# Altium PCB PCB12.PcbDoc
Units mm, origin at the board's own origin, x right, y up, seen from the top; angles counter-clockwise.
Board outline 101.6 x 53.34 mm, 4 copper layers (TOP, GND, SIG, BOTTOM), stack 1.586 mm thick; 3 components, 243 nets, 56 pads, 0 vias.
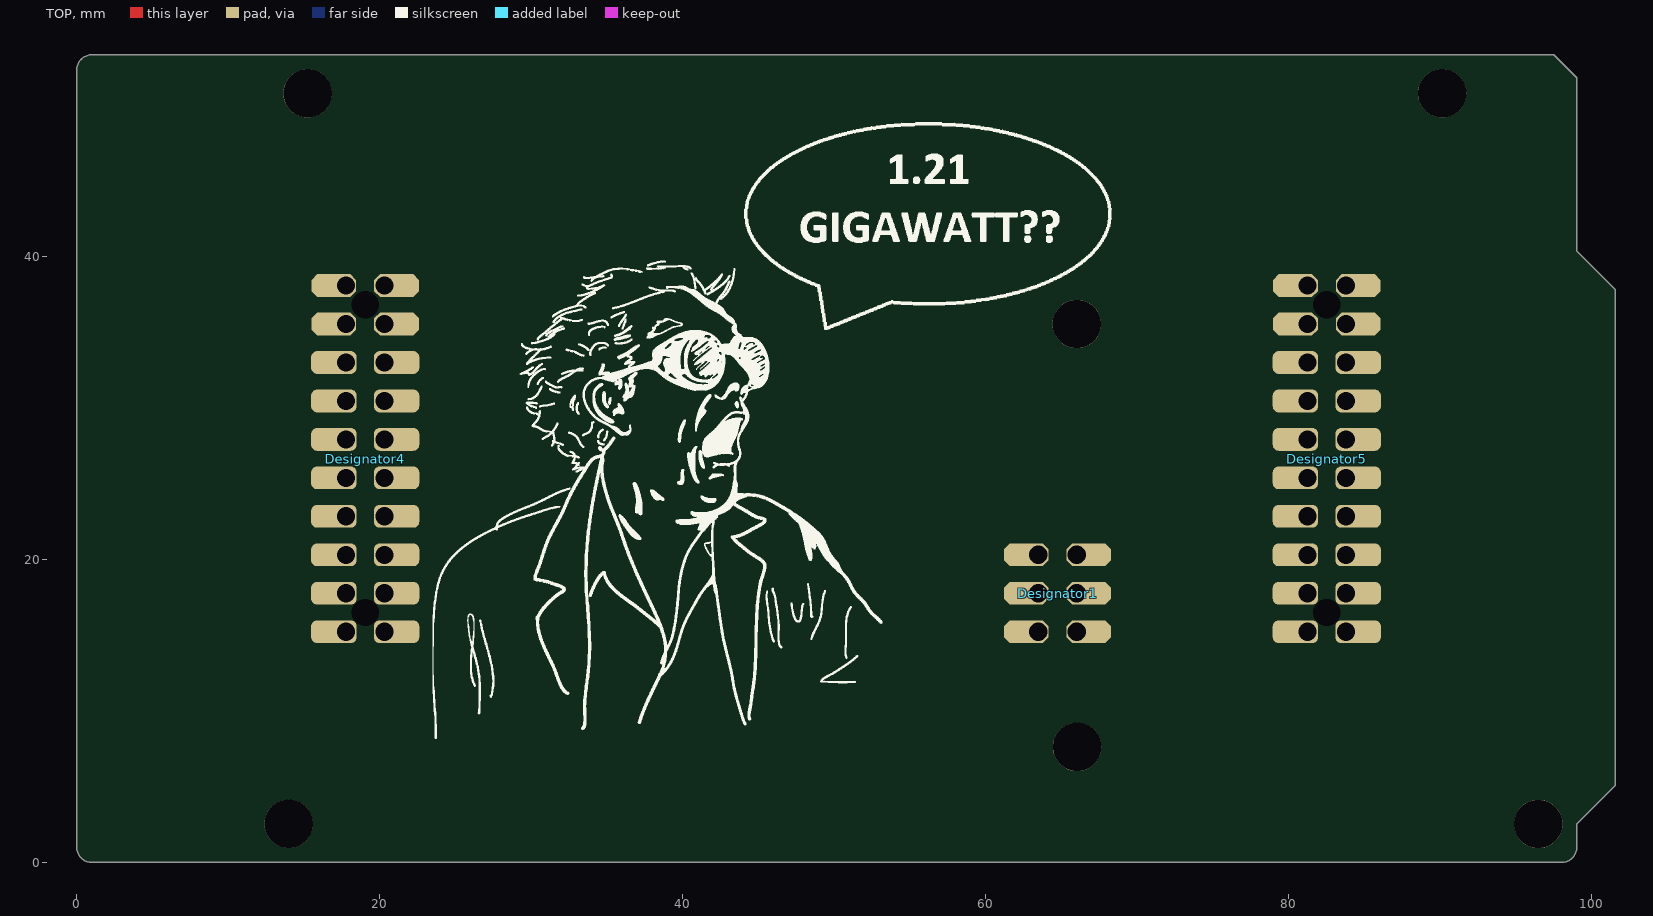
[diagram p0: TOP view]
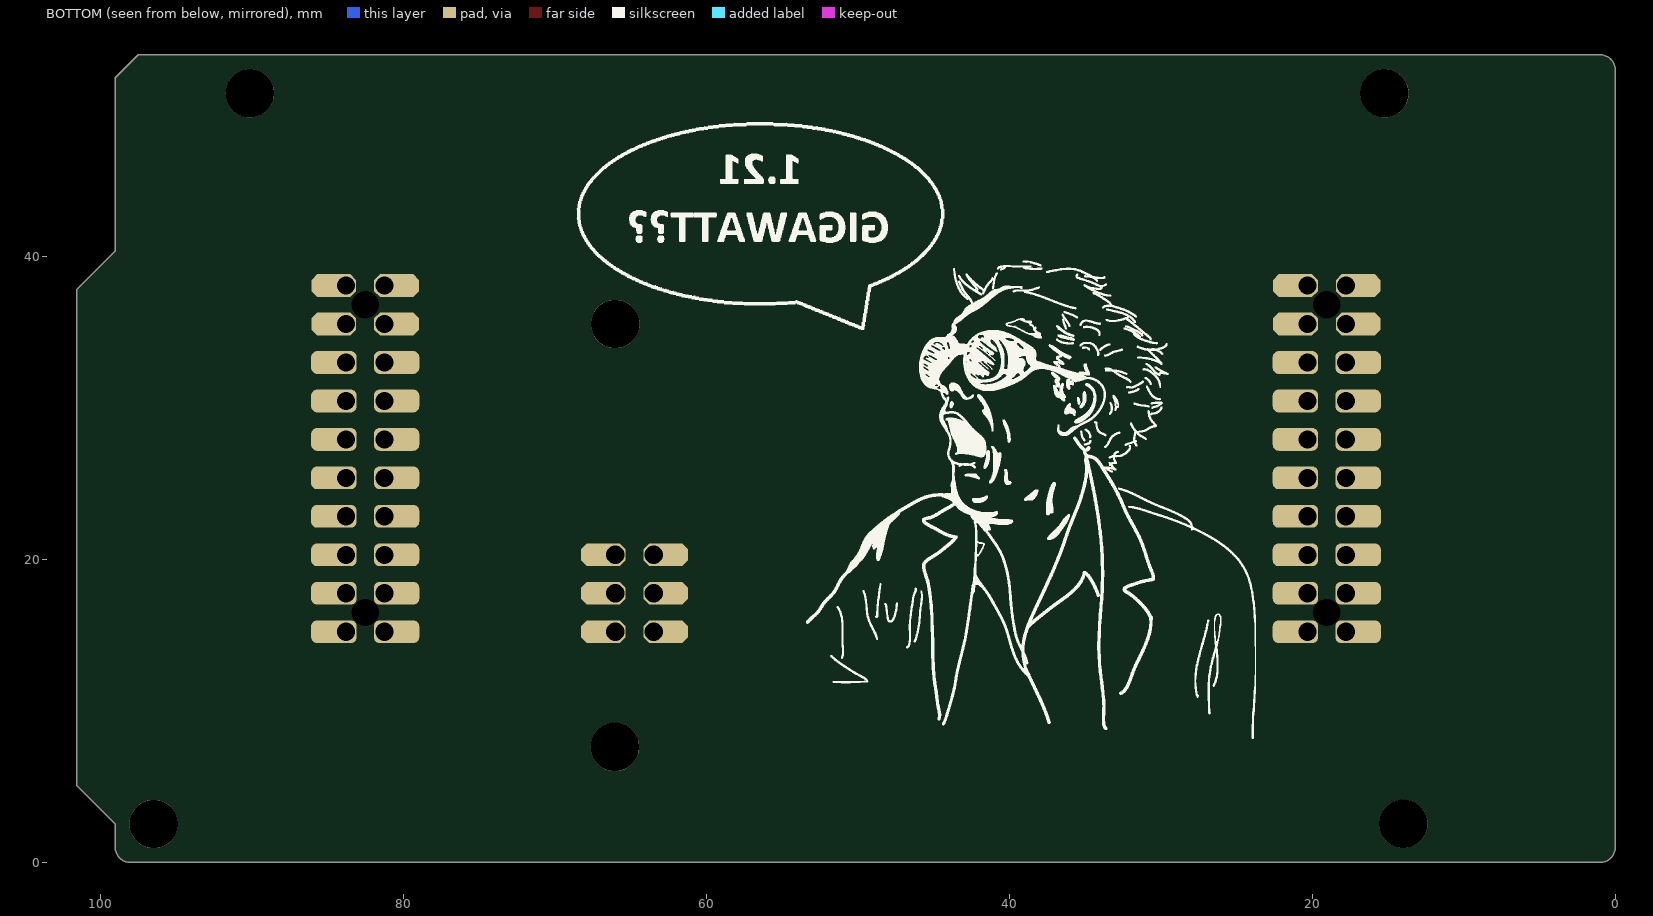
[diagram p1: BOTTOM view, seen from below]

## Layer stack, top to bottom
Top Solder: solder mask 0.0102, Solder Resist, Dk 3.5
TOP: signal copper 0.018
Dielectric 1: prepreg 0.14, PP-014, Dk 4.2
GND: signal copper 0.035
Dielectric2: core 1.2, FR-4, Dk 4.8
SIG: signal copper 0.035
Dielectric3: prepreg 0.14, PP-014, Dk 4.2
BOTTOM: signal copper 0.018
Bottom Solder: solder mask 0.0102, Solder Resist, Dk 3.5

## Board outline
0,1 0,52.34 cw(c1,52.34) 1,53.34 97.536,53.34 99.06,51.816 99.06,40.386 101.6,37.846 101.6,5.08 99.06,2.54 99.06,1 cw(c98.06,1) 98.06,0 1,0 cw(c1,1)

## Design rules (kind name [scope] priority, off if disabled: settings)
BoardOutlineClearance Silks [(OnLayer('Top Overlay') OR OnLayer('Bottom Overlay'))] p1: gap=0.1 ignorepadtopadclearanceinfootprint=FALSE
BoardOutlineClearance [All] p2: gap=0.3 ignorepadtopadclearanceinfootprint=FALSE
Clearance COPPER_0.3mm [All] p1: gap=0.127 ignorepadtopadclearanceinfootprint=FALSE except(0.3: Arc-Fill Arc-Poly Arc-Region Track-Fill Track-Poly Track-Region SMDPad-Fill SMDPad-Poly SMDPad-Region THPad-Fill THPad-Poly THPad-Region Via-Fill Via-Poly Via-Region Fill-Fill Fill-Poly Fill-Region Poly-Poly Poly-Region Region-Region)
Clearance "Generic clearance 0.127mm" [All] p2: gap=0.127 ignorepadtopadclearanceinfootprint=FALSE
ComponentClearance [All] p1: gap=0.2 collisioncheckmode=3 verticalgap=0 showdistances=TRUE
DiffPairsRouting USB [InDifferentialPairClass('USB')] p1: maxlimit=0.254 minlimit=0.15 mostfreqgap=0.254 toplayer_maxgap=0.15 toplayer_prefgap=0.15 toplayer_minwidth=0.15 toplayer_maxwidth=0.21 toplayer_prefwidth=0.2 midlayer2_mingap=0.24 midlayer2_maxgap=0.24 midlayer2_prefgap=0.24 midlayer2_minwidth=0.15 midlayer2_maxwidth=0.15 midlayer2_prefwidth=0.15 bottomlayer_maxgap=0.15 bottomlayer_prefgap=0.15 bottomlayer_minwidth=0.15 bottomlayer_maxwidth=0.21 bottomlayer_prefwidth=0.2 impedanceprofiledriven=TRUE impedanceprofileid={E6B00C31-4C8E-439C-824F-D2B2CDC26F9C} impedanceprofilevalue=90.000000 maxuncoupledlength=12.7
Height [All] p1: minheight=0 maxheight=30 prefheight=12.7
HoleSize [All] p1: absolutevalues=TRUE maxlimit=20 minlimit=0.3 maxpercent=80.000 minpercent=20.000
HoleToHoleClearance [All] p1: gap=0.25 allowstackedmicrovias=FALSE
MinimumAnnularRing [All] p1: minimumring=0.15
PlaneConnect [All] p1: pad.planeconnectstyle=Relief pad.reliefexpansion=0.508 pad.reliefentries=4 pad.reliefconductorwidth=0.254 pad.reliefairgap=0.254 via.planeconnectstyle=Direct via.reliefexpansion=0.508 via.reliefentries=4 via.reliefconductorwidth=0.254 via.reliefairgap=0.254
PolygonConnect [All] p1: thpad.connectstyle=Relief thpad.reliefconductorwidth=0.2 thpad.reliefentries=4 thpad.polygonreliefangle="90 Angle" thpad.airgapwidth=0.254 smdpad.connectstyle=Relief smdpad.reliefconductorwidth=0.2 smdpad.reliefentries=4 smdpad.polygonreliefangle="90 Angle" smdpad.airgapwidth=0.254 via.connectstyle=Direct via.reliefconductorwidth=0.254 via.reliefentries=4 via.polygonreliefangle="90 Angle" via.airgapwidth=0.254
RoomDefinition AUDIO [InComponentClass('AUDIO')] p1: confinementstyle=ConfineIn formatcopy=TRUE lockcomponents=FALSE outline 102.7,0.5 179.2,0.5 179.2,30 102.7,30
RoomDefinition Wifi [InComponentClass('Wifi')] p2: confinementstyle=ConfineIn formatcopy=TRUE lockcomponents=FALSE outline -40.4,-40.4 10.4,-40.4 10.4,-15 -40.4,-15
RoomDefinition TOP [InComponentClass('TOP')] p3: confinementstyle=ConfineIn formatcopy=TRUE lockcomponents=FALSE outline 102.7,1.5 112.4,1.5 112.4,12.5 102.7,12.5
RoomDefinition HEADERS [InComponentClass('HEADERS')] p4: confinementstyle=ConfineIn formatcopy=TRUE lockcomponents=FALSE outline 103.6,3.6 145.6,3.6 145.6,51.6 103.6,51.6
RoomDefinition STM32H747 [InComponentClass('STM32H747')] p5: confinementstyle=ConfineIn formatcopy=TRUE lockcomponents=FALSE outline 57.6,-10.4 61.6,-10.4 61.6,-6.4 57.6,-6.4
RoutingVias StandardVias [All] p1: holewidth=0.2 width=0.4 viastyle="Through Hole" minholewidth=0.2 minwidth=0.4 maxholewidth=0.2 maxwidth=0.4
SMDToCorner [All] p1: distance=39370
SilkToSilkClearance [All] p1: silktosilkclearance=0.2
SilkToSolderMaskClearance [IsPad] p1: minsilkscreentomaskgap=0.15 clearancetoexposedcopper=TRUE
SolderMaskExpansion VIAtented [IsVia] p1: expansion=0.102 istentingtop=TRUE
SolderMaskExpansion [All] p2: expansion=0.05 istentingtop=FALSE
UnRoutedNet [All] p1: checkbadconnections=TRUE
ViasUnderSMD [All] p1: allowed=FALSE
Width StandardTraces [All] p1: maxlimit=5 minlimit=0.127 preferedwidth=0.15
21 further rules are at their usual default settings.

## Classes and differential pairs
net class "50 ohm": NetC1V_1 NetC2V_1
component class Wifi: R18

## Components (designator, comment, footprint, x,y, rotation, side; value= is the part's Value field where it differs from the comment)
Designator1 "Comment" HLE-103-02-F-DV 64.77,17.779 r270 top
Designator4 "Comment" HLE-110-02-F-DV 19.05,26.669 r270 top
Designator5 "Comment" HLE-110-02-F-DV 82.55,26.669 r270 top

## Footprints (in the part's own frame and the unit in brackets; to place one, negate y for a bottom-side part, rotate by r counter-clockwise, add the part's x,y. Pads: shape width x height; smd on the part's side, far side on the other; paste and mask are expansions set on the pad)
HLE-103-02-F-DV [mm]
  oct 1.5x2.95 hole 1.2 copper offset 0,-0.8 mask+0.02: 1(-2.54,-1.27) 3(0,-1.27) 5(2.54,-1.27)
  oct 1.5x2.95 hole 1.2 copper offset 0,0.8 mask+0.02: 2(-2.54,1.27) 4(0,1.27) 6(2.54,1.27)
  body extent -3.81,-3.29 3.81,3.29, height 3.71
HLE-110-02-F-DV [mm]
  round 0 hole 1.8 unplated paste-5: 0(-10.16,0) 0(10.16,0)
  oct 1.5x2.95 hole 1.2 copper offset 0,-0.8 mask+0.02: 1(-11.43,-1.27) 3(-8.89,-1.27)
  oct 1.5x2.95 hole 1.2 copper offset 0,0.8 mask+0.02: 2(-11.43,1.27) 4(-8.89,1.27)
  rrect50% 1.5x3 hole 1.2 copper offset 0,-0.8 mask+0.02: 5(-6.35,-1.27) 7(-3.81,-1.27) 9(-1.27,-1.27) 11(1.27,-1.27) 13(3.81,-1.27) 15(6.356,-1.27) 17(8.89,-1.27) 19(11.43,-1.27)
  rrect50% 1.5x3 hole 1.2 copper offset 0,0.8 mask+0.02: 6(-6.35,1.27) 8(-3.81,1.27) 10(-1.27,1.27) 12(1.27,1.27) 14(3.81,1.27) 16(6.356,1.27) 18(8.89,1.27) 20(11.43,1.27)
  body extent -12.7,-3.29 12.7,3.29, height 3.71

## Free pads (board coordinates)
  round 3.2 hole 3.2 unplated: MH1(96.52,2.54) MH2(15.24,50.8) MH3(90.17,50.8) MH4(13.996,2.553) MH5(66.04,35.56) MH6(66.066,7.633)

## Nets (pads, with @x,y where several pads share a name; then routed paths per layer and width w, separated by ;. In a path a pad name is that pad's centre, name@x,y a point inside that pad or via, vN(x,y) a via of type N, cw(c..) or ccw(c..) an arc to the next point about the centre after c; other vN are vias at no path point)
+1V8: 
+3V1: 
+3V1SW: 
+3V3: 
AIN2A: 
AIN2B: 
AIN3A: 
AIN3B: 
BLE_CTRL_DEVICE_WAKE: 
BLE_CTRL_HOST_WAKE: 
BLE_CTRL_ON: 
DSI_CK_N: 
DSI_CK_P: 
DSI_D0_N: 
DSI_D0_P: 
DSI_D1_N: 
DSI_D1_P: 
GND: 
HP/LINE_OUTA: 
HP/LINE_OUTB: 
HSU_D_N: 
HSU_D_P: 
MICBIAS: 
NetAUDIO_RST_X: 
NetC1_2: 
NetC1V_1: 
NetC2V_1: 
NetC5V_1: 
NetC12_2: 
NetC30_2: 
NetC31_1: 
NetC31_2: 
NetC33_1: 
NetC46_1: 
NetC48_1: 
NetC49_1: 
NetC50_1: 
NetL1_2: 
NetL1V_1: 
NetR2_1: 
NetR3_1: 
NetR4_2: 
NetR6_1: 
NetR7_1: 
NetR8_2: 
NetR9_1: 
NetR10_2: 
NetR12_1: 
NetR34_2: 
NetR35_2: 
NetR46_1: 
NetR46_2: 
NetU1_J1: 
NetU1_K1: 
NetU1V_2: 
NetU1V_3: 
NetU1V_4: 
NetU1V_5: 
NetU1V_8: 
NetU1V_9: 
NetU1V_10: 
NetU1V_11: 
NetU1V_20: 
NetU1V_22: 
NetU1V_23: 
NetU1V_24: 
NetU1V_25: 
NetU1V_26: 
NetU1V_37: 
NetU2_37: 
NetU3_26: 
PA0: 
PA1: 
PA2: 
PA3: 
PA4: 
PA5: 
PA6: 
PA7: 
PA8: 
PA9: 
PA10: 
PA11: 
PA12: 
PA13: 
PA14: 
PA15: 
PB0: 
PB1: 
PB2: 
PB3: 
PB4: 
PB5: 
PB6: 
PB7: 
PB8: 
PB9: 
PB10: 
PB11: 
PB12: 
PB13: 
PB14: 
PB15: 
PC0: 
PC1: 
PC2: 
PC3: 
PC4: 
PC5: 
PC6: 
PC7: 
PC8: 
PC9: 
PC10: 
PC11: 
PC12: 
PC13: 
PD0: 
PD1: 
PD2: 
PD3: 
PD4: 
PD5: 
PD6: 
PD7: 
PD8: 
PD9: 
PD10: 
PD11: 
PD12: 
PD13: 
PD14: 
PD15: 
PE0: 
PE1: 
PE2: 
PE3: 
PE4: 
PE5: 
PE6: 
PE7: 
PE8: 
PE9: 
PE10: 
PE11: 
PE12: 
PE13: 
PE14: 
PE15: 
PF0: 
PF1: 
PF2: 
PF3: 
PF4: 
PF5: 
PF6: 
PF7: 
PF8: 
PF9: 
PF10: 
PF11: 
PF12: 
PF13: 
PF14: 
PF15: 
PG0: 
PG1: 
PG2: 
PG3: 
PG4: 
PG5: 
PG6: 
PG7: 
PG8: 
PG9: 
PG10: 
PG11: 
PG12: 
PG13: 
PG14: 
PG15: 
PH2: 
PH3: 
PH4: 
PH5: 
PH6: 
PH7: 
PH8: 
PH9: 
PH10: 
PH11: 
PH12: 
PH13: 
PH14: 
PH15: 
PI0: 
PI1: 
PI2: 
PI3: 
PI4: 
PI5: 
PI6: 
PI7: 
PI8: 
PI9: 
PI10: 
PI11: 
PI12: 
PI13: 
PI14: 
PI15: 
PJ0: 
PJ1: 
PJ2: 
PJ3: 
PJ4: 
PJ5: 
PJ6: 
PJ7: 
PJ8: 
PJ9: 
PJ10: 
PJ11: 
PJ12: 
PJ13: 
PJ14: 
PJ15: 
PK0: 
PK1: 
PK2: 
PK3: 
PK4: 
PK5: 
PK6: 
PK7: 
SPKR/HP: 
USB0_D_N: 
USB0_D_P: 
VCAP_A7: 
VCAP_D17: 
VCAP_U11: 
WIFI_CTRL_HOST_WAKE: 
WIFI_CTRL_ON: 
pads on no net: Designator1.1 Designator1.2 Designator1.3 Designator1.4 Designator1.5 Designator1.6 Designator4.0 Designator4.1 Designator4.2 Designator4.3 Designator4.4 Designator4.5 Designator4.6 Designator4.7 Designator4.8 Designator4.9 Designator4.10 Designator4.11 Designator4.12 Designator4.13 Designator4.14 Designator4.15 Designator4.16 Designator4.17 Designator4.18 Designator4.19 Designator4.20 Designator5.0 Designator5.1 Designator5.2 Designator5.3 Designator5.4 Designator5.5 Designator5.6 Designator5.7 Designator5.8 Designator5.9 Designator5.10 Designator5.11 Designator5.12 Designator5.13 Designator5.14 Designator5.15 Designator5.16 Designator5.17 Designator5.18 Designator5.19 Designator5.20

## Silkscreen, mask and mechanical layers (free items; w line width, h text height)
Top Overlay:
  drawing of 86 lines, arcs and shapes, not listed
Bottom Overlay:
  drawing of 86 lines, arcs and shapes, not listed
Route Tool Path:
  lines w2: -1,29.75 -1,22.47 -1,1 ccw(c1,1) 1,-1 42.3,-1 48.8,-1 ; -1,33.75 -1,40.25 -1,52.34 cw(c1,52.34) 1,54.34 41.52,54.34 48.8,54.34 ; 52.8,-1 60.08,-1 98.06,-1 ccw(c98.06,1) 100.06,1 100.06,2.126 102.307,4.373 ; 52.8,54.34 59.3,54.34 97.536,54.34 ; 102.6,19.096 102.6,12.596 102.6,5.08 ; 102.6,23.096 102.6,30.376 102.6,37.846 ; 97.536,54.34 cw(c97.536,53.34) 98.243,54.047 ; 97.536,54.34 cw(c97.536,53.34) 98.243,54.047 ; 98.243,54.047 99.767,52.523 ; 99.767,52.523 cw(c99.06,51.816) 100.06,51.816 ; 99.767,52.523 cw(c99.06,51.816) 100.06,51.816 ; 100.06,51.816 100.06,40.8 102.307,38.553 ; 102.307,4.373 ccw(c101.6,5.08) 102.6,5.08 ; 102.307,4.373 ccw(c101.6,5.08) 102.6,5.08 ; 102.307,38.553 cw(c101.6,37.846) 102.6,37.846 ; 102.307,38.553 cw(c101.6,37.846) 102.6,37.846
Board:
  the board outline again, w0.254
Mechanical 9:
  lines w0.1: 6.194,2.927 7.464,2.927 ; 7.464,1.657 7.464,2.927 ; 7.464,4.197 7.464,2.927 ; 8.734,2.927 7.464,2.927 ; 17.552,50.813 18.822,50.813 ; 18.822,49.543 18.822,50.813 ; 18.822,52.083 18.822,50.813 ; 20.092,50.813 18.822,50.813 ; 26.696,2.553 27.966,2.553 ; 27.966,1.283 27.966,2.553 ; 27.966,3.823 27.966,2.553 ; 29.236,2.553 27.966,2.553 ; 44.476,50.813 45.746,50.813 ; 45.746,49.543 45.746,50.813 ; 45.746,52.083 45.746,50.813 ; 47.016,50.813 45.746,50.813 ; 49.556,2.553 50.826,2.553 ; 50.826,1.283 50.826,2.553 ; 50.826,3.823 50.826,2.553 ; 52.096,2.553 50.826,2.553 ; 62.357,30.48 63.627,30.48 ; 63.627,29.21 63.627,30.48 ; 63.627,31.75 63.627,30.48 ; 64.897,30.48 63.627,30.48 ; 67.336,50.813 68.606,50.813 ; 68.606,49.543 68.606,50.813 ; 68.606,52.083 68.606,50.813 ; 69.876,50.813 68.606,50.813 ; 72.416,2.553 73.686,2.553 ; 73.686,1.283 73.686,2.553 ; 73.686,3.823 73.686,2.553 ; 74.956,2.553 73.686,2.553 ; 92.71,50.799 93.98,50.799 ; 93.98,49.529 93.98,50.799 ; 93.98,52.069 93.98,50.799 ; 95.25,50.799 93.98,50.799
